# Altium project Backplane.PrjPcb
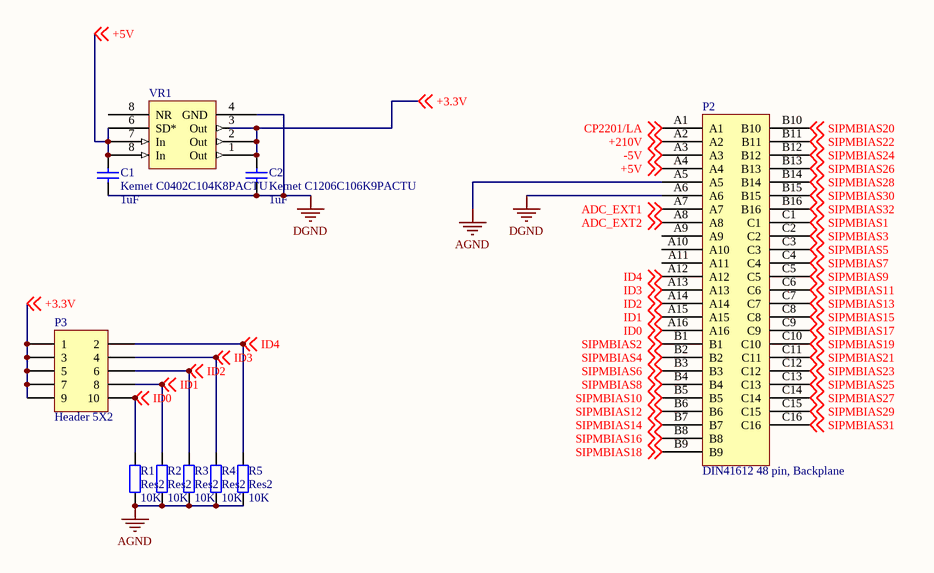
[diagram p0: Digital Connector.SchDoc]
3 sheets, 22 parts. Net scope: global (net labels, ports and power ports of the same name join across sheets).
Board file: Backplane.PcbDoc
Sheets:
  Digital Connector.SchDoc
  Analog Connector.SchDoc
  LEMO.SchDoc

## Sheet Digital Connector.SchDoc
size A

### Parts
C1  Kemet C0402C104K8PACTU  value 1uF  [0402]
C2  Kemet C1206C106K9PACTU  value 1uF  [0402]
P2  DIN41612 48 pin, Backplane  [EURO2.54-2V48]
P3  Header 5X2  [HDR2X5]
R1  Res2  value 10K  [1005[0402]]
R2  Res2  value 10K  [1005[0402]]
R3  Res2  value 10K  [1005[0402]]
R4  Res2  value 10K  [1005[0402]]
R5  Res2  value 10K  [1005[0402]]
VR1  (no value)  [RM-8]

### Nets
AGND: P2.A5 R1.1 R2.1 R3.1 R4.1 R5.1
DGND: C1.1 C2.1 P2.A6 VR1.4(GND)
+3.3V: C2.2 P3.1 P3.3 P3.5 P3.7 P3.9 VR1.1(Out) VR1.2(Out) VR1.3(Out) ; off-sheet +3.3V
+5V: C1.2 P2.A4 VR1.6(SD*) VR1.7(In) VR1.8(In) ; off-sheet +5V
+210V: P2.A2 ; off-sheet +210V
-5V: P2.A3 ; off-sheet -5V
ADC_EXT1: P2.A7 ; off-sheet ADC_EXT1
ADC_EXT2: P2.A8 ; off-sheet ADC_EXT2
CP2201/LA: P2.A1 ; off-sheet CP2201/LA
ID0: P2.A16 P3.10 R1.2 ; off-sheet ID0
ID1: P2.A15 P3.8 R2.2 ; off-sheet ID1
ID2: P2.A14 P3.6 R3.2 ; off-sheet ID2
ID3: P2.A13 P3.4 R4.2 ; off-sheet ID3
ID4: P2.A12 P3.2 R5.2 ; off-sheet ID4
SIPMBIAS1: P2.C1 ; off-sheet SIPMBIAS1
SIPMBIAS2: P2.B1 ; off-sheet SIPMBIAS2
SIPMBIAS3: P2.C2 ; off-sheet SIPMBIAS3
SIPMBIAS4: P2.B2 ; off-sheet SIPMBIAS4
SIPMBIAS5: P2.C3 ; off-sheet SIPMBIAS5
SIPMBIAS6: P2.B3 ; off-sheet SIPMBIAS6
SIPMBIAS7: P2.C4 ; off-sheet SIPMBIAS7
SIPMBIAS8: P2.B4 ; off-sheet SIPMBIAS8
SIPMBIAS9: P2.C5 ; off-sheet SIPMBIAS9
SIPMBIAS10: P2.B5 ; off-sheet SIPMBIAS10
SIPMBIAS11: P2.C6 ; off-sheet SIPMBIAS11
SIPMBIAS12: P2.B6 ; off-sheet SIPMBIAS12
SIPMBIAS13: P2.C7 ; off-sheet SIPMBIAS13
SIPMBIAS14: P2.B7 ; off-sheet SIPMBIAS14
SIPMBIAS15: P2.C8 ; off-sheet SIPMBIAS15
SIPMBIAS16: P2.B8 ; off-sheet SIPMBIAS16
SIPMBIAS17: P2.C9 ; off-sheet SIPMBIAS17
SIPMBIAS18: P2.B9 ; off-sheet SIPMBIAS18
SIPMBIAS19: P2.C10 ; off-sheet SIPMBIAS19
SIPMBIAS20: P2.B10 ; off-sheet SIPMBIAS20
SIPMBIAS21: P2.C11 ; off-sheet SIPMBIAS21
SIPMBIAS22: P2.B11 ; off-sheet SIPMBIAS22
SIPMBIAS23: P2.C12 ; off-sheet SIPMBIAS23
SIPMBIAS24: P2.B12 ; off-sheet SIPMBIAS24
SIPMBIAS25: P2.C13 ; off-sheet SIPMBIAS25
SIPMBIAS26: P2.B13 ; off-sheet SIPMBIAS26
SIPMBIAS27: P2.C14 ; off-sheet SIPMBIAS27
SIPMBIAS28: P2.B14 ; off-sheet SIPMBIAS28
SIPMBIAS29: P2.C15 ; off-sheet SIPMBIAS29
SIPMBIAS30: P2.B15 ; off-sheet SIPMBIAS30
SIPMBIAS31: P2.C16 ; off-sheet SIPMBIAS31
SIPMBIAS32: P2.B16 ; off-sheet SIPMBIAS32

Not connected (* = marked no-connect by the designer): P2 A9 A10 A11

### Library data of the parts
C1 C2 = Cap: Capacitor
P3 = Header 5X2: Header, 5-Pin, Dual row
R1-R5 = Res2: Resistor
VR1 = ADP3335

## Sheet Analog Connector.SchDoc
size A
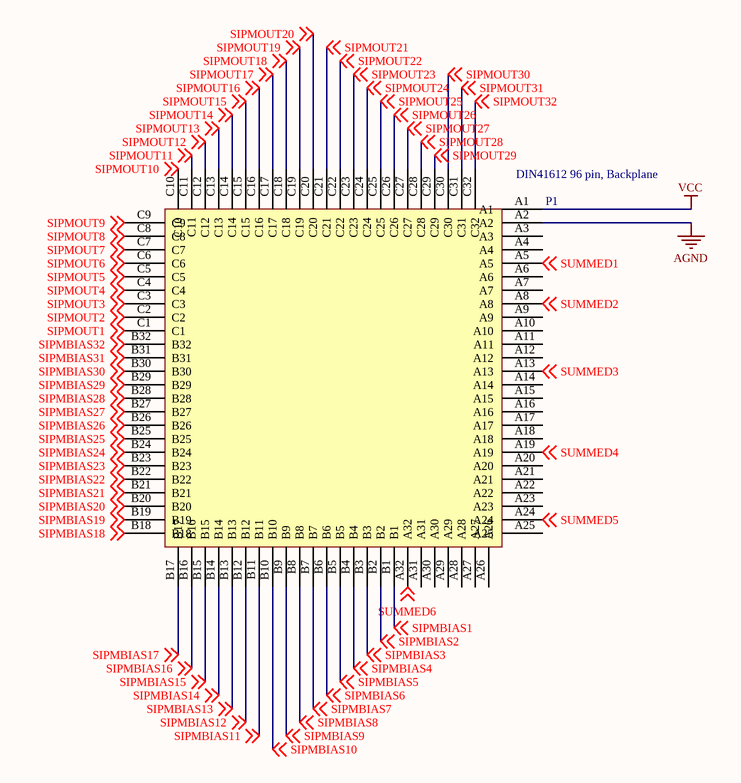
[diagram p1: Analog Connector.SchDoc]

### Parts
P1  DIN41612 96 pin, Backplane  [EURO2.54-2V96]

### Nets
AGND: P1.A2
VCC: P1.A1
SIPMBIAS1: P1.B1 ; off-sheet SIPMBIAS1
SIPMBIAS2: P1.B2 ; off-sheet SIPMBIAS2
SIPMBIAS3: P1.B3 ; off-sheet SIPMBIAS3
SIPMBIAS4: P1.B4 ; off-sheet SIPMBIAS4
SIPMBIAS5: P1.B5 ; off-sheet SIPMBIAS5
SIPMBIAS6: P1.B6 ; off-sheet SIPMBIAS6
SIPMBIAS7: P1.B7 ; off-sheet SIPMBIAS7
SIPMBIAS8: P1.B8 ; off-sheet SIPMBIAS8
SIPMBIAS9: P1.B9 ; off-sheet SIPMBIAS9
SIPMBIAS10: P1.B10 ; off-sheet SIPMBIAS10
SIPMBIAS11: P1.B11 ; off-sheet SIPMBIAS11
SIPMBIAS12: P1.B12 ; off-sheet SIPMBIAS12
SIPMBIAS13: P1.B13 ; off-sheet SIPMBIAS13
SIPMBIAS14: P1.B14 ; off-sheet SIPMBIAS14
SIPMBIAS15: P1.B15 ; off-sheet SIPMBIAS15
SIPMBIAS16: P1.B16 ; off-sheet SIPMBIAS16
SIPMBIAS17: P1.B17 ; off-sheet SIPMBIAS17
SIPMBIAS18: P1.B18 ; off-sheet SIPMBIAS18
SIPMBIAS19: P1.B19 ; off-sheet SIPMBIAS19
SIPMBIAS20: P1.B20 ; off-sheet SIPMBIAS20
SIPMBIAS21: P1.B21 ; off-sheet SIPMBIAS21
SIPMBIAS22: P1.B22 ; off-sheet SIPMBIAS22
SIPMBIAS23: P1.B23 ; off-sheet SIPMBIAS23
SIPMBIAS24: P1.B24 ; off-sheet SIPMBIAS24
SIPMBIAS25: P1.B25 ; off-sheet SIPMBIAS25
SIPMBIAS26: P1.B26 ; off-sheet SIPMBIAS26
SIPMBIAS27: P1.B27 ; off-sheet SIPMBIAS27
SIPMBIAS28: P1.B28 ; off-sheet SIPMBIAS28
SIPMBIAS29: P1.B29 ; off-sheet SIPMBIAS29
SIPMBIAS30: P1.B30 ; off-sheet SIPMBIAS30
SIPMBIAS31: P1.B31 ; off-sheet SIPMBIAS31
SIPMBIAS32: P1.B32 ; off-sheet SIPMBIAS32
SIPMOUT1: P1.C1 ; off-sheet SIPMOUT1
SIPMOUT2: P1.C2 ; off-sheet SIPMOUT2
SIPMOUT3: P1.C3 ; off-sheet SIPMOUT3
SIPMOUT4: P1.C4 ; off-sheet SIPMOUT4
SIPMOUT5: P1.C5 ; off-sheet SIPMOUT5
SIPMOUT6: P1.C6 ; off-sheet SIPMOUT6
SIPMOUT7: P1.C7 ; off-sheet SIPMOUT7
SIPMOUT8: P1.C8 ; off-sheet SIPMOUT8
SIPMOUT9: P1.C9 ; off-sheet SIPMOUT9
SIPMOUT10: P1.C10 ; off-sheet SIPMOUT10
SIPMOUT11: P1.C11 ; off-sheet SIPMOUT11
SIPMOUT12: P1.C12 ; off-sheet SIPMOUT12
SIPMOUT13: P1.C13 ; off-sheet SIPMOUT13
SIPMOUT14: P1.C14 ; off-sheet SIPMOUT14
SIPMOUT15: P1.C15 ; off-sheet SIPMOUT15
SIPMOUT16: P1.C16 ; off-sheet SIPMOUT16
SIPMOUT17: P1.C17 ; off-sheet SIPMOUT17
SIPMOUT18: P1.C18 ; off-sheet SIPMOUT18
SIPMOUT19: P1.C19 ; off-sheet SIPMOUT19
SIPMOUT20: P1.C20 ; off-sheet SIPMOUT20
SIPMOUT21: P1.C21 ; off-sheet SIPMOUT21
SIPMOUT22: P1.C22 ; off-sheet SIPMOUT22
SIPMOUT23: P1.C23 ; off-sheet SIPMOUT23
SIPMOUT24: P1.C24 ; off-sheet SIPMOUT24
SIPMOUT25: P1.C25 ; off-sheet SIPMOUT25
SIPMOUT26: P1.C26 ; off-sheet SIPMOUT26
SIPMOUT27: P1.C27 ; off-sheet SIPMOUT27
SIPMOUT28: P1.C28 ; off-sheet SIPMOUT28
SIPMOUT29: P1.C29 ; off-sheet SIPMOUT29
SIPMOUT30: P1.C30 ; off-sheet SIPMOUT30
SIPMOUT31: P1.C31 ; off-sheet SIPMOUT31
SIPMOUT32: P1.C32 ; off-sheet SIPMOUT32
SUMMED1: P1.A5 ; off-sheet SUMMED1
SUMMED2: P1.A8 ; off-sheet SUMMED2
SUMMED3: P1.A13 ; off-sheet SUMMED3
SUMMED4: P1.A19 ; off-sheet SUMMED4
SUMMED5: P1.A24 ; off-sheet SUMMED5
SUMMED6: P1.A32 ; off-sheet SUMMED6

Not connected (* = marked no-connect by the designer): P1 A3 A4 A6 A7 A9 A10 A11 A12 A14 A15 A16 A17 A18 A20 A21 A22 A23 A25 A26 A27 A28 A29 A30 A31

## Sheet LEMO.SchDoc
size A
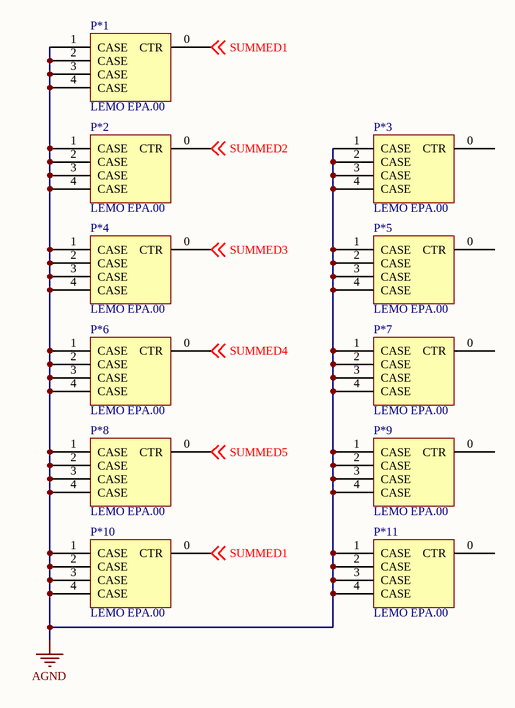
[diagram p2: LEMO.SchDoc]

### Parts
P*1  LEMO EPA.00  [LEMO EPA.00]
P*2  LEMO EPA.00  [LEMO EPA.00]
P*3  LEMO EPA.00  [LEMO EPA.00]
P*4  LEMO EPA.00  [LEMO EPA.00]
P*5  LEMO EPA.00  [LEMO EPA.00]
P*6  LEMO EPA.00  [LEMO EPA.00]
P*7  LEMO EPA.00  [LEMO EPA.00]
P*8  LEMO EPA.00  [LEMO EPA.00]
P*9  LEMO EPA.00  [LEMO EPA.00]
P*10  LEMO EPA.00  [LEMO EPA.00]
P*11  LEMO EPA.00  [LEMO EPA.00]

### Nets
AGND: P*1.1(CASE) P*1.2(CASE) P*1.3(CASE) P*1.4(CASE) P*2.1(CASE) P*2.2(CASE) P*2.3(CASE) P*2.4(CASE) P*3.1(CASE) P*3.2(CASE) P*3.3(CASE) P*3.4(CASE) P*4.1(CASE) P*4.2(CASE) P*4.3(CASE) P*4.4(CASE) P*5.1(CASE) P*5.2(CASE) P*5.3(CASE) P*5.4(CASE) P*6.1(CASE) P*6.2(CASE) P*6.3(CASE) P*6.4(CASE) P*7.1(CASE) P*7.2(CASE) P*7.3(CASE) P*7.4(CASE) P*8.1(CASE) P*8.2(CASE) P*8.3(CASE) P*8.4(CASE) P*9.1(CASE) P*9.2(CASE) P*9.3(CASE) P*9.4(CASE) P*10.1(CASE) P*10.2(CASE) P*10.3(CASE) P*10.4(CASE) P*11.1(CASE) P*11.2(CASE) P*11.3(CASE) P*11.4(CASE)
SUMMED1: P*1.0(CTR) P*10.0(CTR) ; off-sheet SUMMED1
SUMMED2: P*2.0(CTR) ; off-sheet SUMMED2
SUMMED3: P*4.0(CTR) ; off-sheet SUMMED3
SUMMED4: P*6.0(CTR) ; off-sheet SUMMED4
SUMMED5: P*8.0(CTR) ; off-sheet SUMMED5

Not connected (* = marked no-connect by the designer): P*3 0(CTR); P*5 0(CTR); P*7 0(CTR); P*9 0(CTR); P*11 0(CTR)

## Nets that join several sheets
AGND: Digital Connector (6 pins), Analog Connector (P1.A2), LEMO (44 pins)
SIPMBIAS1: Digital Connector (P2.C1), Analog Connector (P1.B1)
SIPMBIAS2: Digital Connector (P2.B1), Analog Connector (P1.B2)
SIPMBIAS3: Digital Connector (P2.C2), Analog Connector (P1.B3)
SIPMBIAS4: Digital Connector (P2.B2), Analog Connector (P1.B4)
SIPMBIAS5: Digital Connector (P2.C3), Analog Connector (P1.B5)
SIPMBIAS6: Digital Connector (P2.B3), Analog Connector (P1.B6)
SIPMBIAS7: Digital Connector (P2.C4), Analog Connector (P1.B7)
SIPMBIAS8: Digital Connector (P2.B4), Analog Connector (P1.B8)
SIPMBIAS9: Digital Connector (P2.C5), Analog Connector (P1.B9)
SIPMBIAS10: Digital Connector (P2.B5), Analog Connector (P1.B10)
SIPMBIAS11: Digital Connector (P2.C6), Analog Connector (P1.B11)
SIPMBIAS12: Digital Connector (P2.B6), Analog Connector (P1.B12)
SIPMBIAS13: Digital Connector (P2.C7), Analog Connector (P1.B13)
SIPMBIAS14: Digital Connector (P2.B7), Analog Connector (P1.B14)
SIPMBIAS15: Digital Connector (P2.C8), Analog Connector (P1.B15)
SIPMBIAS16: Digital Connector (P2.B8), Analog Connector (P1.B16)
SIPMBIAS17: Digital Connector (P2.C9), Analog Connector (P1.B17)
SIPMBIAS18: Digital Connector (P2.B9), Analog Connector (P1.B18)
SIPMBIAS19: Digital Connector (P2.C10), Analog Connector (P1.B19)
SIPMBIAS20: Digital Connector (P2.B10), Analog Connector (P1.B20)
SIPMBIAS21: Digital Connector (P2.C11), Analog Connector (P1.B21)
SIPMBIAS22: Digital Connector (P2.B11), Analog Connector (P1.B22)
SIPMBIAS23: Digital Connector (P2.C12), Analog Connector (P1.B23)
SIPMBIAS24: Digital Connector (P2.B12), Analog Connector (P1.B24)
SIPMBIAS25: Digital Connector (P2.C13), Analog Connector (P1.B25)
SIPMBIAS26: Digital Connector (P2.B13), Analog Connector (P1.B26)
SIPMBIAS27: Digital Connector (P2.C14), Analog Connector (P1.B27)
SIPMBIAS28: Digital Connector (P2.B14), Analog Connector (P1.B28)
SIPMBIAS29: Digital Connector (P2.C15), Analog Connector (P1.B29)
SIPMBIAS30: Digital Connector (P2.B15), Analog Connector (P1.B30)
SIPMBIAS31: Digital Connector (P2.C16), Analog Connector (P1.B31)
SIPMBIAS32: Digital Connector (P2.B16), Analog Connector (P1.B32)
SUMMED1: Analog Connector (P1.A5), LEMO (P*1.0 P*10.0)
SUMMED2: Analog Connector (P1.A8), LEMO (P*2.0)
SUMMED3: Analog Connector (P1.A13), LEMO (P*4.0)
SUMMED4: Analog Connector (P1.A19), LEMO (P*6.0)
SUMMED5: Analog Connector (P1.A24), LEMO (P*8.0)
